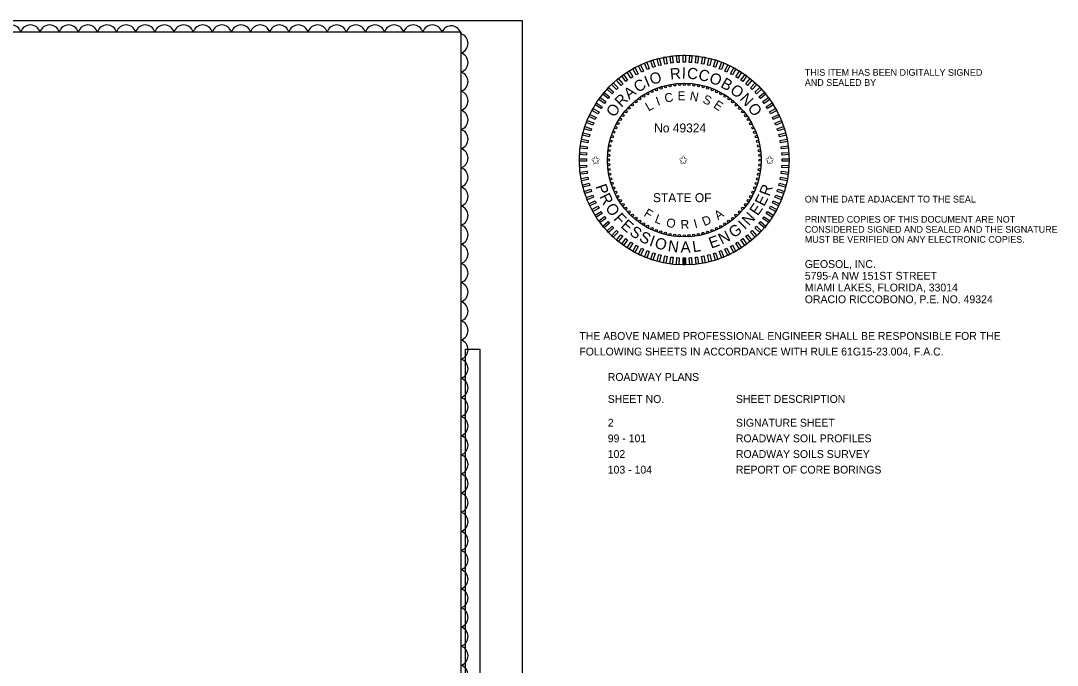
# Model space of a CAD drawing. Extents: x -811.3 to -790.1, y -2211.9 to -2188.9.
# Drawn here: x -799.32 to -790.06, y -2194.66 to -2188.9 of the extents above; entities that cross this region are included whole.
import ezdxf

# ---------------------------------------------------------------- set-up
doc = ezdxf.new("R2010")
doc.units = 0
for name, color, linetype in [('Cloud_dp', 7, 'Continuous'), ('Logo_dp', 7, 'Continuous'), ('NonPlottingEle_dp', 7, 'Continuous'), ('PlotBorder_dp', 7, 'Continuous'), ('ScratchEle_dp', 7, 'Continuous'), ('SheetBorder_dp', 7, 'Continuous'), ('TextMisc', 7, 'Continuous'), ('TextNotes', 7, 'Continuous')]:
    doc.layers.add(name, color=color, linetype=linetype)

msp = doc.modelspace()

# ---------------------------------------------------------------- linework, layer by layer
at = {"layer": 'Cloud_dp'}
for centre, radius, start, end in [((-799.4061, -2189.0276), 0.0897, 17.5, 162.5), ((-799.235, -2189.0276), 0.0897, 17.5, 162.5), ((-799.0639, -2189.0276), 0.0897, 17.5, 162.5), ((-798.8928, -2189.0276), 0.0897, 17.5, 162.5), ((-798.7216, -2189.0276), 0.0897, 17.5, 162.5), ((-798.5505, -2189.0276), 0.0897, 17.5, 162.5), ((-798.3794, -2189.0276), 0.0897, 17.5, 162.5), ((-798.2083, -2189.0276), 0.0897, 17.5, 162.5), ((-798.0371, -2189.0276), 0.0897, 17.5, 162.5), ((-797.866, -2189.0276), 0.0897, 17.5, 162.5), ((-797.6949, -2189.0276), 0.0897, 17.5, 162.5), ((-797.5238, -2189.0276), 0.0897, 17.5, 162.5), ((-797.3527, -2189.0276), 0.0897, 17.5, 162.5), ((-797.1815, -2189.0276), 0.0897, 17.5, 162.5), ((-797.0104, -2189.0276), 0.0897, 17.5, 162.5), ((-796.8393, -2189.0276), 0.0897, 17.5, 162.5), ((-796.6682, -2189.0276), 0.0897, 17.5, 162.5), ((-796.497, -2189.0276), 0.0897, 17.5, 162.5), ((-796.3259, -2189.0276), 0.0897, 17.5, 162.5), ((-796.1548, -2189.0276), 0.0897, 17.5, 162.5), ((-795.9837, -2189.0276), 0.0897, 17.5, 162.5), ((-795.8126, -2189.0276), 0.0897, 17.5, 162.5), ((-795.6414, -2189.0276), 0.0897, 17.5, 162.5), ((-795.4735, -2189.036), 0.0896, 11.74536, 156.74536), ((-795.4127, -2189.1033), 0.0897, 287.5, 72.5), ((-795.4127, -2189.2745), 0.0897, 287.5, 72.5), ((-795.4127, -2189.4456), 0.0897, 287.5, 72.5), ((-795.4127, -2189.6167), 0.0897, 287.5, 72.5), ((-795.4127, -2189.7878), 0.0897, 287.5, 72.5), ((-795.4127, -2189.959), 0.0897, 287.5, 72.5), ((-795.4127, -2190.1301), 0.0897, 287.5, 72.5), ((-795.4127, -2190.3012), 0.0897, 287.5, 72.5), ((-795.4127, -2190.4723), 0.0897, 287.5, 72.5), ((-795.4127, -2190.6434), 0.0897, 287.5, 72.5), ((-795.4127, -2190.8146), 0.0897, 287.5, 72.5), ((-795.4127, -2190.9857), 0.0897, 287.5, 72.5), ((-795.4127, -2191.1568), 0.0897, 287.5, 72.5), ((-795.4127, -2191.3279), 0.0897, 287.5, 72.5), ((-795.4127, -2191.4991), 0.0897, 287.5, 72.5), ((-795.4127, -2191.6702), 0.0897, 287.5, 72.5), ((-795.4127, -2191.8413), 0.0897, 287.5, 72.5), ((-795.4127, -2192.0124), 0.0897, 287.5, 72.5), ((-795.4127, -2192.1835), 0.0897, 287.5, 72.5), ((-795.4127, -2192.3547), 0.0897, 287.5, 72.5), ((-795.4127, -2192.5258), 0.0897, 287.5, 72.5), ((-795.4127, -2192.6969), 0.0897, 287.5, 72.5), ((-795.4127, -2192.868), 0.0897, 287.5, 72.5), ((-795.4127, -2193.0392), 0.0897, 287.5, 72.5), ((-795.4127, -2193.2103), 0.0897, 287.5, 72.5), ((-795.4127, -2193.3814), 0.0897, 287.5, 72.5), ((-795.4127, -2193.5525), 0.0897, 287.5, 72.5), ((-795.4127, -2193.7237), 0.0897, 287.5, 72.5), ((-795.4127, -2193.8948), 0.0897, 287.5, 72.5), ((-795.4127, -2194.0659), 0.0897, 287.5, 72.5), ((-795.4127, -2194.237), 0.0897, 287.5, 72.5), ((-795.4127, -2194.4081), 0.0897, 287.5, 72.5), ((-795.4127, -2194.5793), 0.0897, 287.5, 72.5), ((-795.4127, -2194.7504), 0.0897, 287.5, 72.5)]:
    msp.add_arc(centre, radius, start, end, dxfattribs=at)
at = {"layer": 'Logo_dp'}
for p, q in [((-793.3999, -2191.0843), (-793.4001, -2191.0218)), ((-793.3899, -2191.0843), (-793.3901, -2191.0218)), ((-793.3799, -2191.0843), (-793.3801, -2191.0218))]:
    msp.add_line(p, q, dxfattribs=at)
for points in [[(-793.5976, -2189.2967), (-793.6172, -2189.3018), (-793.6327, -2189.2413), (-793.6132, -2189.2363)], [(-793.5438, -2189.2854), (-793.5637, -2189.2892), (-793.5754, -2189.2278), (-793.5555, -2189.224)], [(-793.4895, -2189.2774), (-793.5095, -2189.2799), (-793.5173, -2189.218), (-793.4973, -2189.2155)], [(-793.4347, -2189.2729), (-793.4548, -2189.2741), (-793.4587, -2189.2118), (-793.4386, -2189.2106)], [(-793.3797, -2189.2718), (-793.3999, -2189.2718), (-793.3999, -2189.2093), (-793.3797, -2189.2093)], [(-793.3248, -2189.2741), (-793.3449, -2189.2729), (-793.341, -2189.2106), (-793.3209, -2189.2118)], [(-793.2701, -2189.28), (-793.2901, -2189.2774), (-793.2823, -2189.2155), (-793.2623, -2189.218)], [(-793.2159, -2189.2892), (-793.2357, -2189.2854), (-793.224, -2189.2241), (-793.2042, -2189.2279)], [(-793.1624, -2189.3018), (-793.182, -2189.2968), (-793.1664, -2189.2363), (-793.1469, -2189.2413)], [(-793.8025, -2189.3751), (-793.8202, -2189.3848), (-793.8503, -2189.3301), (-793.8326, -2189.3204)], [(-793.7532, -2189.3507), (-793.7715, -2189.3593), (-793.7981, -2189.3028), (-793.7798, -2189.2942)], [(-793.7025, -2189.3295), (-793.7213, -2189.3369), (-793.7443, -2189.2789), (-793.7255, -2189.2714)], [(-793.6506, -2189.3115), (-793.6698, -2189.3177), (-793.6891, -2189.2583), (-793.6699, -2189.2521)], [(-793.1098, -2189.3178), (-793.129, -2189.3115), (-793.1097, -2189.2521), (-793.0905, -2189.2584)], [(-793.0583, -2189.337), (-793.0771, -2189.3295), (-793.0541, -2189.2715), (-793.0353, -2189.2789)], [(-793.0081, -2189.3594), (-793.0264, -2189.3508), (-792.9998, -2189.2943), (-792.9815, -2189.3029)], [(-792.9594, -2189.3849), (-792.9771, -2189.3752), (-792.947, -2189.3205), (-792.9293, -2189.3302)], [(-793.9398, -2189.4661), (-793.9554, -2189.479), (-793.9952, -2189.4309), (-793.9796, -2189.418)], [(-793.896, -2189.4329), (-793.9123, -2189.4448), (-793.949, -2189.3943), (-793.9327, -2189.3824)], [(-793.8502, -2189.4025), (-793.8672, -2189.4134), (-793.9007, -2189.3606), (-793.8836, -2189.3498)], [(-792.9124, -2189.4135), (-792.9295, -2189.4026), (-792.896, -2189.3499), (-792.879, -2189.3607)], [(-792.8673, -2189.4449), (-792.8836, -2189.433), (-792.8469, -2189.3825), (-792.8306, -2189.3944)], [(-792.8243, -2189.4791), (-792.8398, -2189.4662), (-792.8, -2189.4181), (-792.7845, -2189.431)], [(-794.0208, -2189.5404), (-794.0346, -2189.5551), (-794.0801, -2189.5124), (-794.0663, -2189.4976)], [(-793.9815, -2189.502), (-793.9962, -2189.5158), (-794.0389, -2189.4703), (-794.0242, -2189.4565)], [(-792.7835, -2189.5159), (-792.7982, -2189.5021), (-792.7554, -2189.4566), (-792.7407, -2189.4704)], [(-792.745, -2189.5552), (-792.7589, -2189.5405), (-792.7133, -2189.4978), (-792.6995, -2189.5125)], [(-794.0918, -2189.6242), (-794.1037, -2189.6406), (-794.1542, -2189.6039), (-794.1423, -2189.5875)], [(-794.0576, -2189.5812), (-794.0705, -2189.5968), (-794.1186, -2189.5569), (-794.1057, -2189.5414)], [(-792.7092, -2189.5969), (-792.722, -2189.5813), (-792.6739, -2189.5415), (-792.6611, -2189.5571)], [(-792.676, -2189.6407), (-792.6878, -2189.6244), (-792.6373, -2189.5877), (-792.6255, -2189.604)], [(-794.1518, -2189.7163), (-794.1615, -2189.734), (-794.2162, -2189.7039), (-794.2065, -2189.6863)], [(-794.1232, -2189.6693), (-794.1341, -2189.6864), (-794.1868, -2189.6529), (-794.176, -2189.6359)], [(-792.6456, -2189.6865), (-792.6564, -2189.6695), (-792.6037, -2189.636), (-792.5929, -2189.6531)], [(-792.6182, -2189.7342), (-792.6279, -2189.7165), (-792.5732, -2189.6864), (-792.5635, -2189.7041)], [(-794.1997, -2189.8152), (-794.2071, -2189.834), (-794.2652, -2189.811), (-794.2578, -2189.7922)], [(-794.1773, -2189.765), (-794.1859, -2189.7833), (-794.2424, -2189.7567), (-794.2338, -2189.7384)], [(-792.5938, -2189.7835), (-792.6024, -2189.7652), (-792.5459, -2189.7386), (-792.5373, -2189.7569)], [(-792.5726, -2189.8342), (-792.58, -2189.8154), (-792.5219, -2189.7924), (-792.5145, -2189.8112)], [(-794.2189, -2189.8667), (-794.2252, -2189.8859), (-794.2846, -2189.8666), (-794.2783, -2189.8474)], [(-792.5545, -2189.8861), (-792.5608, -2189.8669), (-792.5014, -2189.8476), (-792.4952, -2189.8668)], [(-794.2475, -2189.9728), (-794.2513, -2189.9927), (-794.3126, -2189.981), (-794.3088, -2189.9611)], [(-794.2349, -2189.9193), (-794.2399, -2189.9389), (-794.3004, -2189.9234), (-794.2954, -2189.9038)], [(-792.5398, -2189.9391), (-792.5448, -2189.9195), (-792.4844, -2189.904), (-792.4793, -2189.9235)], [(-792.5284, -2189.9929), (-792.5322, -2189.973), (-792.4709, -2189.9613), (-792.4671, -2189.9812)], [(-794.2567, -2190.027), (-794.2593, -2190.0471), (-794.3212, -2190.0392), (-794.3187, -2190.0192)], [(-792.5205, -2190.0472), (-792.523, -2190.0272), (-792.4611, -2190.0194), (-792.4585, -2190.0394)], [(-794.2649, -2190.1366), (-794.2649, -2190.1568), (-794.3274, -2190.1568), (-794.3274, -2190.1366)], [(-794.2626, -2190.0817), (-794.2638, -2190.1018), (-794.3261, -2190.0979), (-794.3249, -2190.0778)], [(-792.5159, -2190.102), (-792.5172, -2190.0819), (-792.4549, -2190.078), (-792.4536, -2190.0981)], [(-792.5149, -2190.157), (-792.5149, -2190.1368), (-792.4524, -2190.1368), (-792.4524, -2190.157)], [(-794.2638, -2190.1916), (-794.2626, -2190.2117), (-794.3249, -2190.2157), (-794.3261, -2190.1955)], [(-794.2593, -2190.2464), (-794.2568, -2190.2664), (-794.3187, -2190.2742), (-794.3212, -2190.2542)], [(-792.523, -2190.2666), (-792.5205, -2190.2466), (-792.4586, -2190.2544), (-792.4611, -2190.2744)], [(-792.5172, -2190.2119), (-792.516, -2190.1918), (-792.4536, -2190.1957), (-792.4549, -2190.2158)], [(-794.2513, -2190.3008), (-794.2475, -2190.3206), (-794.3089, -2190.3323), (-794.3127, -2190.3125)], [(-792.5323, -2190.3208), (-792.5285, -2190.301), (-792.4671, -2190.3127), (-792.4709, -2190.3325)], [(-794.24, -2190.3546), (-794.2349, -2190.3741), (-794.2954, -2190.3896), (-794.3004, -2190.3701)], [(-794.2252, -2190.4075), (-794.219, -2190.4267), (-794.2784, -2190.446), (-794.2846, -2190.4268)], [(-792.5608, -2190.4269), (-792.5546, -2190.4077), (-792.4952, -2190.427), (-792.5014, -2190.4462)], [(-792.5449, -2190.3743), (-792.5399, -2190.3547), (-792.4794, -2190.3703), (-792.4844, -2190.3898)], [(-794.2072, -2190.4595), (-794.1998, -2190.4782), (-794.2578, -2190.5012), (-794.2653, -2190.4824)], [(-794.186, -2190.5102), (-794.1774, -2190.5284), (-794.2339, -2190.555), (-794.2425, -2190.5367)], [(-792.6025, -2190.5286), (-792.5939, -2190.5103), (-792.5374, -2190.5369), (-792.546, -2190.5552)], [(-792.5801, -2190.4784), (-792.5726, -2190.4596), (-792.5146, -2190.4826), (-792.522, -2190.5014)], [(-794.1616, -2190.5594), (-794.1519, -2190.5771), (-794.2066, -2190.6072), (-794.2163, -2190.5895)], [(-794.1342, -2190.6071), (-794.1233, -2190.6241), (-794.1761, -2190.6576), (-794.1869, -2190.6405)], [(-792.6565, -2190.6243), (-792.6457, -2190.6072), (-792.593, -2190.6407), (-792.6038, -2190.6577)], [(-792.628, -2190.5773), (-792.6183, -2190.5596), (-792.5636, -2190.5897), (-792.5733, -2190.6074)], [(-794.1038, -2190.6529), (-794.0919, -2190.6692), (-794.1424, -2190.7059), (-794.1543, -2190.6896)], [(-794.0706, -2190.6967), (-794.0577, -2190.7123), (-794.1058, -2190.7521), (-794.1187, -2190.7365)], [(-792.7222, -2190.7124), (-792.7093, -2190.6969), (-792.6612, -2190.7367), (-792.674, -2190.7522)], [(-792.688, -2190.6694), (-792.6761, -2190.653), (-792.6256, -2190.6898), (-792.6374, -2190.7061)], [(-794.0347, -2190.7384), (-794.0209, -2190.7531), (-794.0664, -2190.7958), (-794.0802, -2190.7811)], [(-793.9963, -2190.7777), (-793.9816, -2190.7915), (-794.0243, -2190.837), (-794.0391, -2190.8232)], [(-793.9555, -2190.8145), (-793.9399, -2190.8274), (-793.9797, -2190.8755), (-793.9953, -2190.8627)], [(-792.7983, -2190.7917), (-792.7836, -2190.7778), (-792.7409, -2190.8234), (-792.7556, -2190.8372)], [(-792.759, -2190.7532), (-792.7452, -2190.7385), (-792.6997, -2190.7813), (-792.7135, -2190.796)], [(-793.9125, -2190.8487), (-793.8961, -2190.8606), (-793.9328, -2190.9111), (-793.9492, -2190.8993)], [(-793.8674, -2190.8802), (-793.8503, -2190.891), (-793.8838, -2190.9437), (-793.9008, -2190.9329)], [(-792.9296, -2190.8911), (-792.9126, -2190.8803), (-792.8791, -2190.933), (-792.8962, -2190.9438)], [(-792.8838, -2190.8607), (-792.8675, -2190.8488), (-792.8308, -2190.8994), (-792.8471, -2190.9112)], [(-792.84, -2190.8275), (-792.8244, -2190.8147), (-792.7846, -2190.8628), (-792.8002, -2190.8756)], [(-793.8204, -2190.9087), (-793.8027, -2190.9184), (-793.8328, -2190.9731), (-793.8504, -2190.9634)], [(-793.7717, -2190.9342), (-793.7534, -2190.9428), (-793.78, -2190.9993), (-793.7983, -2190.9907)], [(-793.7215, -2190.9566), (-793.7027, -2190.9641), (-793.7257, -2191.0221), (-793.7445, -2191.0147)], [(-793.67, -2190.9759), (-793.6508, -2190.9821), (-793.6701, -2191.0415), (-793.6893, -2191.0352)], [(-793.6174, -2190.9918), (-793.5978, -2190.9968), (-793.6133, -2191.0573), (-793.6329, -2191.0523)], [(-793.1821, -2190.9969), (-793.1626, -2190.9919), (-793.1471, -2191.0523), (-793.1666, -2191.0574)], [(-793.1292, -2190.9822), (-793.11, -2190.9759), (-793.0907, -2191.0353), (-793.1099, -2191.0415)], [(-793.0772, -2190.9641), (-793.0585, -2190.9567), (-793.0355, -2191.0148), (-793.0543, -2191.0222)], [(-793.0265, -2190.9429), (-793.0083, -2190.9343), (-792.9817, -2190.9908), (-792.9999, -2190.9994)], [(-792.9773, -2190.9185), (-792.9596, -2190.9088), (-792.9295, -2190.9635), (-792.9472, -2190.9732)], [(-793.5639, -2191.0044), (-793.544, -2191.0082), (-793.5557, -2191.0695), (-793.5756, -2191.0658)], [(-793.5097, -2191.0137), (-793.4896, -2191.0162), (-793.4975, -2191.0781), (-793.5175, -2191.0756)], [(-793.455, -2191.0195), (-793.4348, -2191.0207), (-793.4388, -2191.0831), (-793.4589, -2191.0818)], [(-793.4001, -2191.0218), (-793.3799, -2191.0218), (-793.3799, -2191.0843), (-793.4001, -2191.0843)], [(-793.3451, -2191.0208), (-793.325, -2191.0195), (-793.321, -2191.0818), (-793.3412, -2191.0831)], [(-793.2903, -2191.0162), (-793.2703, -2191.0137), (-793.2625, -2191.0756), (-793.2825, -2191.0782)], [(-793.2359, -2191.0082), (-793.2161, -2191.0045), (-793.2044, -2191.0658), (-793.2242, -2191.0696)]]:
    msp.add_lwpolyline(points, close=True, dxfattribs=at)
for centre in [(-793.6388, -2189.5167), (-793.5987, -2189.5023), (-793.5578, -2189.4905), (-793.5163, -2189.4812), (-793.4742, -2189.4746), (-793.4319, -2189.4706), (-793.3893, -2189.4693), (-793.3468, -2189.4707), (-793.3044, -2189.4748), (-793.2624, -2189.4814), (-793.2209, -2189.4908), (-793.18, -2189.5027), (-793.14, -2189.5171), (-793.7876, -2189.5984), (-793.7524, -2189.5745), (-793.7158, -2189.5529), (-793.6778, -2189.5336), (-793.1009, -2189.5341), (-793.063, -2189.5534), (-793.0264, -2189.5751), (-792.9912, -2189.5991), (-793.8834, -2189.6826), (-793.8532, -2189.6526), (-793.8213, -2189.6245), (-792.9576, -2189.6252), (-792.9257, -2189.6533), (-792.8956, -2189.6835), (-793.9616, -2189.7833), (-793.9376, -2189.7481), (-793.9115, -2189.7145), (-792.8675, -2189.7154), (-792.8415, -2189.7491), (-792.8176, -2189.7843), (-794.0196, -2189.8969), (-794.0026, -2189.8578), (-793.9833, -2189.8199), (-792.7959, -2189.8209), (-792.7767, -2189.8589), (-794.0459, -2189.9778), (-794.034, -2189.9369), (-792.7598, -2189.8979), (-792.7454, -2189.938), (-792.7336, -2189.9789), (-794.0619, -2190.0613), (-794.0552, -2190.0193), (-792.7243, -2190.0204), (-792.7177, -2190.0625), (-794.0674, -2190.1462), (-794.066, -2190.1037), (-792.7137, -2190.1048), (-792.7124, -2190.1474), (-794.0661, -2190.1888), (-794.0621, -2190.2312), (-792.7178, -2190.2323), (-792.7138, -2190.1899), (-794.0555, -2190.2732), (-794.0462, -2190.3147), (-794.0344, -2190.3556), (-792.7457, -2190.3567), (-792.7338, -2190.3158), (-792.7245, -2190.2743), (-794.02, -2190.3957), (-794.0031, -2190.4348), (-792.7771, -2190.4358), (-792.7602, -2190.3967), (-793.9838, -2190.4727), (-793.9622, -2190.5093), (-793.9383, -2190.5446), (-792.8421, -2190.5455), (-792.8182, -2190.5103), (-792.7965, -2190.4737), (-793.9122, -2190.5782), (-793.8841, -2190.6102), (-792.8964, -2190.611), (-792.8682, -2190.5791), (-793.8541, -2190.6403), (-793.8222, -2190.6684), (-793.7885, -2190.6946), (-793.7534, -2190.7185), (-793.0274, -2190.7191), (-792.9921, -2190.6952), (-792.9585, -2190.6692), (-792.9265, -2190.641), (-793.7168, -2190.7402), (-793.6788, -2190.7596), (-793.6398, -2190.7765), (-793.5998, -2190.7909), (-793.5589, -2190.8029), (-793.5174, -2190.8122), (-793.4754, -2190.8189), (-793.433, -2190.8229), (-793.3899, -2190.8243), (-793.3479, -2190.823), (-793.3055, -2190.819), (-793.2635, -2190.8124), (-793.222, -2190.8031), (-793.1811, -2190.7913), (-793.141, -2190.7769), (-793.1019, -2190.76), (-793.064, -2190.7408)]:
    msp.add_circle(centre, 0.01, dxfattribs=at)
at = {"layer": 'NonPlottingEle_dp'}
for radius in [0.9375, 0.6875]:
    msp.add_circle((-793.3899, -2190.1468), radius, dxfattribs=at)
at = {"layer": 'PlotBorder_dp'}
msp.add_lwpolyline([(-811.3358, -2199.5006), (-794.8358, -2199.5006), (-794.8358, -2188.9006), (-811.3358, -2188.9006)], close=True, dxfattribs=at)
at = {"layer": 'ScratchEle_dp'}
msp.add_lwpolyline([(-795.3456, -2191.8382), (-795.218, -2191.8382), (-795.218, -2198.6801), (-795.3456, -2198.6801)], close=True, dxfattribs=at)
at = {"layer": 'SheetBorder_dp'}
for p, q in [((-810.7858, -2189.0006), (-795.3858, -2189.0006)), ((-795.3858, -2189.0006), (-795.3858, -2199.4006))]:
    msp.add_line(p, q, dxfattribs=at)

# ---------------------------------------------------------------- texts
at = {"layer": 'Logo_dp'}
for s, height, rotation, p in [('R', 0.1, 5.37227, (-793.5127, -2189.4277)), ('I', 0.1, 357.55092, (-793.4137, -2189.4176)), ('C', 0.1, 354.01772, (-793.3688, -2189.4175)), ('I', 0.1, 22.64568, (-793.7207, -2189.4966)), ('O', 0.1, 19.11248, (-793.68, -2189.4774)), ('C', 0.1, 346.28093, (-793.2708, -2189.427)), ('O', 0.1, 338.54413, (-793.175, -2189.4496)), ('B', 0.1, 329.88327, (-793.0724, -2189.4899)), ('A', 0.1, 38.14947, (-793.8825, -2189.6087)), ('C', 0.1, 30.38248, (-793.8053, -2189.547)), ('O', 0.1, 322.27934, (-792.9883, -2189.5377)), ('R', 0.1, 45.97082, (-793.9512, -2189.6807)), ('I', 0.08, 20.01168, (-793.6256, -2189.6627)), ('C', 0.08, 12.20255, (-793.5576, -2189.6352)), ('E', 0.08, 0.41861, (-793.4496, -2189.6117)), ('N', 0.08, 349.29143, (-793.3452, -2189.6103)), ('S', 0.08, 337.02207, (-793.2322, -2189.632)), ('N', 0.1, 313.61848, (-792.9011, -2189.6051)), ('O', 0.1, 54.63169, (-794.015, -2189.7705)), ('L', 0.08, 30.40215, (-793.709, -2189.7132)), ('E', 0.08, 325.86633, (-793.1356, -2189.6722)), ('O', 0.1, 305.36831, (-792.8285, -2189.6809)), ('P', 0.1, 289.40551, (-794.1846, -2190.3814)), ('R', 0.1, 296.14576, (-794.1516, -2190.473)), ('R', 0.1, 69.5134, (-792.6297, -2190.4765)), ('E', 0.1, 55.42892, (-792.7328, -2190.6516)), ('E', 0.1, 62.47116, (-792.6759, -2190.5672)), ('O', 0.1, 303.96711, (-794.1001, -2190.5737)), ('F', 0.1, 312.62798, (-794.0277, -2190.6757)), ('F', 0.08, 328.72408, (-793.7579, -2190.6434)), ('A', 0.08, 34.49917, (-793.088, -2190.6862)), ('N', 0.1, 47.17876, (-792.812, -2190.7407)), ('E', 0.1, 319.07833, (-793.9643, -2190.744)), ('L', 0.08, 339.29159, (-793.6606, -2190.7025)), ('O', 0.08, 349.68206, (-793.556, -2190.7422)), ('R', 0.08, 2.33977, (-793.4215, -2190.7641)), ('I', 0.08, 14.20366, (-793.2939, -2190.7574)), ('D', 0.08, 22.01279, (-793.2118, -2190.7387)), ('I', 0.1, 43.64556, (-792.8497, -2190.7751)), ('S', 0.1, 326.12056, (-793.8867, -2190.81)), ('S', 0.1, 333.193, (-793.8013, -2190.8661)), ('N', 0.1, 26.86136, (-793.0542, -2190.9044)), ('G', 0.1, 35.11153, (-792.9489, -2190.8483)), ('I', 0.1, 340.26543, (-793.7096, -2190.9113)), ('O', 0.1, 343.79863, (-793.6619, -2190.9295)), ('N', 0.1, 352.45949, (-793.5409, -2190.9615)), ('A', 0.1, 0.70966, (-793.4224, -2190.9748)), ('L', 0.1, 8.47665, (-793.3102, -2190.9716)), ('E', 0.1, 19.81912, (-793.1496, -2190.9398))]:
    msp.add_text(s, height=height, rotation=rotation, dxfattribs=at).set_placement(p)
for s, p in [('No 49324', (-793.6588, -2189.8996)), ('✩', (-794.2249, -2190.1848)), ('✩', (-793.4401, -2190.1848)), ('✩', (-792.6683, -2190.1848)), ('STATE OF', (-793.6696, -2190.523))]:
    msp.add_text(s, height=0.08, dxfattribs=at).set_placement(p)
at = {"layer": 'TextMisc'}
for s, height, p in [('AND SEALED BY', 0.06, (-792.3122, -2189.483)), ('THIS ITEM HAS BEEN DIGITALLY SIGNED ', 0.06, (-792.3122, -2189.393)), ('ON THE DATE ADJACENT TO THE SEAL', 0.06, (-792.3122, -2190.5264)), ('PRINTED COPIES OF THIS DOCUMENT ARE NOT ', 0.06, (-792.3122, -2190.7064)), ('CONSIDERED SIGNED AND SEALED AND THE SIGNATURE ', 0.06, (-792.3122, -2190.7964)), ('MUST BE VERIFIED ON ANY ELECTRONIC COPIES.', 0.06, (-792.3122, -2190.8864)), ('GEOSOL, INC.', 0.07, (-792.3122, -2191.1116)), ('5795-A NW 151ST STREET', 0.07, (-792.3122, -2191.2166)), ('MIAMI LAKES, FLORIDA, 33014', 0.07, (-792.3122, -2191.3216)), ('ORACIO RICCOBONO, P.E. NO. 49324', 0.07, (-792.3122, -2191.4266)), ('THE ABOVE NAMED PROFESSIONAL ENGINEER SHALL BE RESPONSIBLE FOR THE ', 0.07, (-794.3274, -2191.7544)), ('FOLLOWING SHEETS IN ACCORDANCE WITH RULE 61G15-23.004, F.A.C.', 0.07, (-794.3274, -2191.8944)), ('ROADWAY PLANS', 0.07, (-794.0737, -2192.1214))]:
    msp.add_text(s, height=height, dxfattribs=at).set_placement(p)
at = {"layer": 'TextNotes'}
for s, p in [('SHEET NO.', (-794.0737, -2192.3184)), ('SHEET DESCRIPTION', (-792.9278, -2192.3184)), ('2', (-794.0737, -2192.5306)), ('SIGNATURE SHEET', (-792.9278, -2192.5306)), ('99 - 101', (-794.0737, -2192.6706)), ('ROADWAY SOIL PROFILES', (-792.9278, -2192.6706)), ('102', (-794.0737, -2192.8106)), ('ROADWAY SOILS SURVEY', (-792.9278, -2192.8106)), ('103 - 104', (-794.0737, -2192.9506)), ('REPORT OF CORE BORINGS', (-792.9278, -2192.9506))]:
    msp.add_text(s, height=0.07, dxfattribs=at).set_placement(p)

doc.saveas('drawing.dxf')
